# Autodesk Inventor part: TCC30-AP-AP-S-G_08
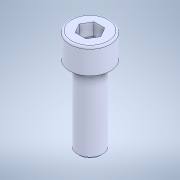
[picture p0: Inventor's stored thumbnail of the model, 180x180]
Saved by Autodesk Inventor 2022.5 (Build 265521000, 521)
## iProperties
Created: 2023-09
Part Number: TCC30-AP-AP-S-G_08
Material: 一般
Document SubType Name: Modeling
Designer: ImaoCorp
Density: 1 g/cm^3
Appearance: 既定
Author: ImaoCorp
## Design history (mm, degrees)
feature "TCC30-AP-AP-S-G_08"
node "ソリッド1"
